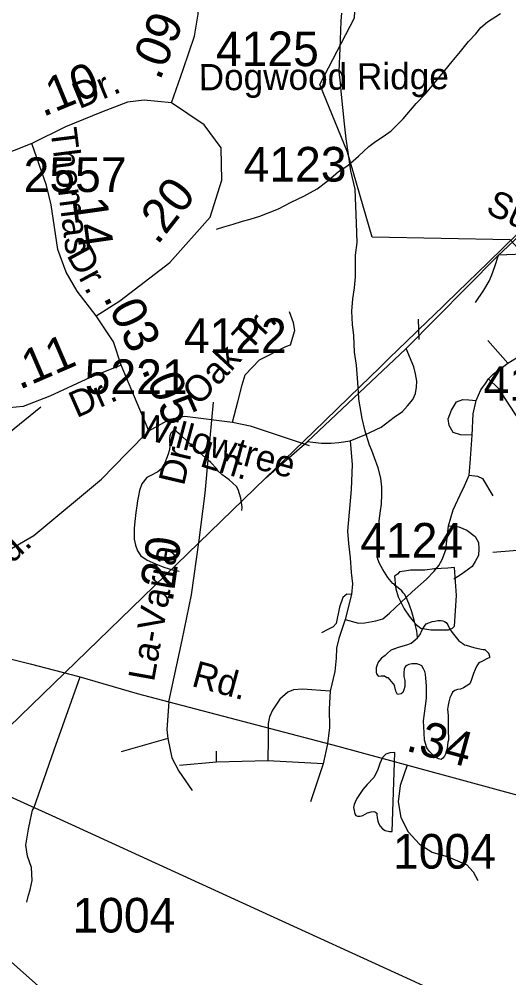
# Model space of a CAD drawing. Extents: x 2169602 to 2449496, y 721995 to 810662.
# Drawn here: x 2387442 to 2389212, y 765731 to 769191 of the extents above; entities that cross this region are included whole.
import ezdxf

# ---------------------------------------------------------------- set-up
doc = ezdxf.new("R2010")
doc.units = 0
doc.layers.add('Default', color=7, linetype='Continuous')

msp = doc.modelspace()

# ---------------------------------------------------------------- linework, layer by layer
at = {"layer": 'Default'}
for p, q in [((2388888.2, 768035.6), (2388885.1, 768108.4)), ((2389208.7, 767949), (2389135.5, 768030.9)), ((2388643, 767114.7), (2388620.1, 767024.6)), ((2387568.8, 766553.9), (2387662.8, 766816.8)), ((2387494.8, 766343.6), (2387568.8, 766553.9)), ((2388156, 766509.2), (2388156, 766548.5)), ((2388156, 766509.2), (2388021.7, 766496.6)), ((2388340.5, 766514.1), (2388156, 766509.2)), ((2388540.4, 766502.6), (2388340.5, 766514.1)), ((2388540.4, 766502.6), (2388494.5, 766366.1))]:
    msp.add_line(p, q, dxfattribs=at)
for points in [[(2386380.1, 765643.4), (2386857.9, 766106.2), (2386916.4, 766162.9), (2386960.4, 766205.5), (2388333.9, 767535.6), (2388482.6, 767665.6), (2388839.5, 768000.9), (2389171, 768336), (2391030.3, 770080.7), (2393764.7, 772758.1), (2394526.4, 773595), (2394852.5, 773868.2), (2394973.7, 773986.6), (2394998.1, 774010.6), (2395018.6, 774030.8), (2395083, 774094), (2395207.8, 774217.2), (2395509.9, 774514.3), (2395511.9, 774516.4), (2395846.4, 774839.9), (2396368, 775322.6), (2396469.9, 775429.5)], [(2391073.6, 764947.2), (2391178.6, 766960.8), (2390837.4, 766875.9), (2390242.1, 766812.3), (2390226.7, 766354.4), (2389410.2, 766177.4), (2389443.8, 768148.7), (2389216.4, 768394.4), (2388718.4, 768404), (2388629, 768711.2), (2388529.1, 768955.2), (2388654.4, 769196.1), (2388670.2, 769505.2), (2388617.3, 769865), (2388811.9, 770134.5), (2389300.7, 770249.9), (2390705.1, 770262.3), (2391005.7, 772988.7), (2392249.8, 773007.3), (2392264.1, 772753.4), (2392724.3, 772714.7), (2392730.4, 771054.6), (2393230.3, 770963)], [(2386380.1, 765643.4), (2386857.9, 766106.2), (2386916.4, 766162.9), (2386960.4, 766205.5), (2388333.9, 767535.6), (2388482.6, 767665.6), (2388839.5, 768000.9), (2389171, 768336), (2391030.3, 770080.7), (2393764.7, 772758.1)], [(2387993.1, 768889.1), (2388034.9, 769009.5), (2388075.7, 769129.9), (2388089.3, 769209.5), (2388084.1, 769344.6)], [(2388155.8, 768433.4), (2388181.9, 768441.2), (2388215.7, 768451.4), (2388249.7, 768461.8), (2388277.4, 768469.7), (2388311.5, 768480), (2388345.7, 768493.9), (2388379.5, 768506.2), (2388425.3, 768530.5), (2388471, 768552.8), (2388519.2, 768578.8), (2388558.9, 768608.8), (2388596.7, 768640.9), (2388630.5, 768663.3), (2388668.7, 768697.4), (2388706.2, 768731.4), (2388730, 768749.7), (2388758.1, 768767.7), (2388786.1, 768787.8), (2388829.6, 768832), (2388877.2, 768886.4), (2388911.2, 768922.2), (2388947.3, 768964.6), (2388980.9, 769006.6), (2389006.8, 769038.8), (2389036.5, 769074.9), (2389066.5, 769110.9), (2389092.3, 769139), (2389110.1, 769161.1), (2389134.3, 769181.4), (2389181.7, 769211.5)], [(2388669.8, 767825), (2388665.7, 767879.5), (2388661.1, 767941.8), (2388653.6, 767989.6), (2388651.1, 768049.6), (2388646.8, 768089.6), (2388644.5, 768137.4), (2388648.4, 768181.4), (2388654.2, 768221.5), (2388657.9, 768261.5), (2388657.9, 768309.4), (2388657.7, 768339.4), (2388663.8, 768385.5), (2388661.3, 768455.3), (2388656.6, 768577.2), (2388640.4, 768643.4), (2388632, 768703), (2388624, 768759.1), (2388617.7, 768813.2), (2388611.5, 768872.9), (2388606.8, 768919), (2388603.1, 768960.9), (2388598.6, 769003), (2388602.5, 769086.8), (2388604.3, 769149), (2388606, 769184.8), (2388607.8, 769213)], [(2387993.1, 768889.1), (2387893.7, 768898.5), (2387833.5, 768891.2), (2387739.3, 768855.6), (2387609.6, 768803.2), (2387487.7, 768742.5)], [(2387721, 768120.5), (2387806.3, 768174.9), (2387986.3, 768313.1), (2388132.8, 768476.5), (2388174.6, 768610.5), (2388172.5, 768726.8), (2388111.3, 768810.5), (2387993.1, 768889.1)], [(2387487.7, 768742.5), (2387231.8, 768641.9), (2386991.7, 768536.2)], [(2387721, 768120.5), (2387651.4, 768209.5), (2387611.7, 768278.6), (2387582.4, 768360.3), (2387557.8, 768521.5), (2387541, 768590.6), (2387487.7, 768742.5)], [(2386380.1, 765643.5), (2386857.9, 766106.2), (2386916.4, 766162.9), (2386960.4, 766205.5), (2388333.9, 767535.6), (2388505.9, 767702.1), (2388676.1, 767867), (2388744, 767932.7), (2388776, 767963.6), (2388815.8, 768002.1), (2388837.1, 768023), (2388922.4, 768105.7), (2388935.7, 768118.4), (2389025.9, 768205.9), (2389135.6, 768312), (2389194.1, 768368.8), (2389200.2, 768374.7), (2389278.4, 768450.3)], [(2389090.8, 768169), (2389121.3, 768212.7), (2389141, 768245.5), (2389150.8, 768268.4), (2389161.5, 768299), (2389174.7, 768339.7)], [(2389208.7, 767949), (2389254.6, 767978.5), (2389299.3, 768014.5), (2389310.3, 768029.8), (2389319, 768049.5), (2389326.6, 768080), (2389338.6, 768149.4), (2389341.9, 768223.7), (2389341.9, 768266.2), (2389339.7, 768290.3), (2389332.1, 768306.6), (2389317.9, 768323), (2389304.8, 768333.9), (2389281.9, 768341.6), (2389264.4, 768342.7), (2389174.7, 768339.7)], [(2387811.5, 767942.5), (2387782.8, 768026.2), (2387721, 768120.5)], [(2388213.5, 767736.9), (2388232.9, 767810.4), (2388248, 767870.9), (2388258.8, 767907.6), (2388310.7, 767961.6), (2388405.7, 768009.2), (2388422.9, 768015.6), (2388438.1, 768067.5), (2388433.7, 768095.6), (2388418.6, 768134.5)], [(2388638.7, 767669.5), (2388691.1, 767690.7), (2388750.1, 767718), (2388797, 767754.1), (2388827.6, 767774.8), (2388846.1, 767795.6), (2388864.7, 767818.5), (2388874.5, 767840.4), (2388877.8, 767863.3), (2388878.9, 767884), (2388874.5, 767911.3), (2388868, 767936.4), (2388840.9, 768002.3)], [(2387811.5, 767942.5), (2387699, 767897.4), (2387553.6, 767830.4), (2387456.8, 767792.7), (2387381.5, 767786.4), (2387288.3, 767802.1)], [(2387911.5, 767704.8), (2387849.2, 767851.4), (2387811.5, 767942.5)], [(2389138.8, 767893.3), (2389156.3, 767910.8), (2389179.2, 767928.3), (2389208.7, 767949)], [(2389094, 767815.2), (2389110.4, 767852.9), (2389127.9, 767875.8), (2389138.8, 767893.3)], [(2389138.8, 767893.3), (2389174.8, 767858.4), (2389205.4, 767809.2), (2389242.6, 767751.9), (2389265.5, 767724.6), (2389278.6, 767707.1)], [(2387983.7, 766727.2), (2388031.1, 766949), (2388065.4, 767112.9), (2388093.2, 767310), (2388114.6, 767480.3), (2388126, 767614), (2388144.9, 767808.8)], [(2388795.9, 767152.8), (2388792.8, 767154.5), (2388774.7, 767176.3), (2388756.3, 767204.2), (2388744.8, 767226.2), (2388738.4, 767242.2), (2388736.4, 767252.3), (2388736.6, 767274.1), (2388736.2, 767292.4), (2388736, 767314.3), (2388738, 767334.3), (2388741.9, 767362.1), (2388743.6, 767380.1), (2388747.5, 767416), (2388751.6, 767440.2), (2388753.2, 767476), (2388753.4, 767502.4), (2388749.3, 767534.2), (2388739.1, 767572.2), (2388726.8, 767608.2), (2388717.1, 767634), (2388708.5, 767653.9), (2388692.5, 767703.8), (2388682.3, 767749.6), (2388674.1, 767791.8), (2388670.2, 767819.6), (2388669.8, 767825)], [(2389078.7, 767690.2), (2389037.3, 767690.7), (2389011, 767699.5), (2388995.8, 767724.6), (2388992.5, 767748.6), (2389004.5, 767780.3), (2389023.1, 767809.8), (2389046, 767818.5), (2389066.7, 767817.4), (2389094, 767815.2)], [(2389078.7, 767690.2), (2389083.1, 767766.1), (2389094, 767815.2)], [(2387520.4, 767790.4), (2387109.2, 767457.9), (2386137.9, 767379.2)], [(2387911.5, 767704.8), (2387986.7, 767747.7), (2388040.7, 767758.5), (2388213.5, 767736.9)], [(2388213.5, 767736.9), (2388277.5, 767723.3), (2388490.5, 767652.2)], [(2386711.3, 766346.6), (2386764.1, 766508.9), (2386866.1, 766897.4), (2386895.4, 766978.1), (2386938.8, 767039.8), (2387000.6, 767112.1), (2387084.3, 767166.5), (2387174.8, 767196.9), (2387283.6, 767212.6), (2387339.1, 767237.7), (2387495, 767327.8), (2387740.4, 767530.9), (2387830.9, 767624.1), (2387911.5, 767704.8)], [(2388155.1, 767569.7), (2388135, 767591.5), (2388115.1, 767607.4), (2388091.1, 767629.3), (2388054.6, 767663.2), (2388024.9, 767690.9), (2388014.6, 767698.9), (2388010.7, 767702.7), (2388006.8, 767704.9), (2387998.6, 767704.9), (2387994.5, 767700.7), (2387991, 767696.8), (2387986.7, 767686.9), (2387985.1, 767676.6), (2387986.9, 767646.7), (2387984.9, 767632.8), (2387980.8, 767620.8), (2387965.2, 767580.6), (2387957.4, 767568.8), (2387943.5, 767556.7), (2387915.6, 767542.7), (2387903.1, 767536.5), (2387885.8, 767514.3), (2387877.6, 767490.4), (2387873.7, 767470.3), (2387869.8, 767452.2), (2387867.8, 767434.3), (2387864.3, 767410.5), (2387860.2, 767378.3), (2387858.4, 767352.2), (2387858.4, 767314.4), (2387862.9, 767292.3), (2387870.5, 767272.4), (2387882.4, 767254.5), (2387904.9, 767238.5), (2387934.8, 767224.6), (2387964.8, 767212.8), (2387996.8, 767203.1), (2388020.4, 767199.1)], [(2389357.3, 765493.2), (2389238.5, 765547.6), (2388843.6, 765729.8), (2388322.2, 765968.2), (2387561.5, 766315.9), (2387500.6, 766343.5), (2387061.4, 766542.1), (2386786.2, 766666.5), (2385752.3, 767165.8), (2385572, 767251), (2385399.7, 767340.2), (2385209.4, 767441.4), (2385079, 767522.7), (2384962.7, 767604.2), (2384887.9, 767663.1)], [(2388483.3, 767666.2), (2388534.9, 767660.7), (2388569.9, 767660.7), (2388597.2, 767662.9), (2388638.7, 767669.5)], [(2388638.7, 767669.5), (2388645.2, 767583.2), (2388641.9, 767493.6), (2388628.8, 767343.5), (2388632.1, 767298.7), (2388638.7, 767246.3), (2388641.9, 767193.3), (2388647.4, 767152.9), (2388643, 767114.7)], [(2389067.8, 767545.5), (2389072.2, 767588.6), (2389078.7, 767690.2)], [(2390536.3, 767677.6), (2390125, 767345.1), (2389153.7, 767266.3)], [(2388246.8, 767417.4), (2388247.8, 767430), (2388243.9, 767461.8), (2388233.4, 767493.8), (2388227.9, 767504), (2388201.2, 767527.8), (2388175.2, 767547.6), (2388161, 767559.5), (2388155.1, 767569.7)], [(2388993.6, 767362.6), (2389010, 767419.9), (2389036.2, 767474.5), (2389051.4, 767507.3), (2389067.8, 767545.5)], [(2389067.8, 767545.5), (2389098.4, 767542.2), (2389117, 767533.5), (2389154.1, 767471.2)], [(2388620.1, 767024.6), (2388668.1, 767011.5), (2388691.1, 767012.6), (2388731.5, 767019.2), (2388756.6, 767026.8), (2388780.6, 767046.5), (2388862.5, 767124), (2388913.9, 767169.3), (2388942.2, 767198.8), (2388958.6, 767219.5), (2388970.6, 767240.3), (2388983.7, 767275.2), (2388993.6, 767362.6)], [(2388993.6, 767362.6), (2389030.7, 767358.2), (2389060.2, 767346.2), (2389089.7, 767324.4), (2389101.7, 767302.5), (2389102.8, 767280.7), (2389101.7, 767255.6), (2389089.7, 767233.7), (2389078.7, 767215.2), (2389039.4, 767186.8), (2389013.2, 767169.3)], [(2389023.2, 767111.3), (2389014.8, 767211.5), (2388991, 767209.4), (2388942.6, 767207), (2388908.8, 767202.8), (2388885, 767202.8), (2388856.9, 767202.5), (2388834.9, 767198.6), (2388816.7, 767196.4), (2388809.1, 767188.3), (2388798.9, 767180.5), (2388799.3, 767170.3), (2388800.9, 767152.6), (2388803, 767134.4), (2388811.6, 767106.4), (2388821.4, 767086.6), (2388833.1, 767062.6), (2388851.4, 767036.7), (2388865.7, 767018.7), (2388877.6, 767004.8), (2388893.8, 766993), (2388929.9, 766987.1), (2388960, 766987.4), (2388994.1, 766987.1), (2389007.8, 766993.2), (2389015.6, 766999.7), (2389023.2, 767111.3)], [(2388881.2, 766958.6), (2388881, 766972.4), (2388879.3, 766982.4), (2388877.1, 766992.4), (2388870.9, 767016.5), (2388864.8, 767038.5), (2388860.7, 767052.1), (2388852.9, 767076.4), (2388844.7, 767096.3), (2388836.3, 767114.3), (2388830.3, 767120), (2388824.6, 767128.2), (2388812.1, 767138.1), (2388802, 767146.2), (2388795.9, 767152.8)], [(2388643, 767114.7), (2388626.7, 767115.8), (2388612.5, 767103.8), (2388599.4, 767068.8), (2388587.3, 767009.3), (2388576.4, 766997.3), (2388557.9, 766987.5), (2388534.9, 766975.5)], [(2386978.7, 767010.8), (2387153.5, 766945.9), (2387482.1, 766864.2), (2387657.9, 766818.1), (2387869.2, 766757.4), (2387983.7, 766727.2)], [(2388620.1, 767024.6), (2388597.2, 766955.8), (2388589.5, 766920.9), (2388588.4, 766884.8), (2388583, 766836.8), (2388566.6, 766765.8)], [(2388881.2, 766958.6), (2388885.3, 766962.4), (2388890.8, 766970.5), (2388897, 766984.6), (2388901.1, 766990.5), (2388907, 767000.5), (2388912.9, 767008.5), (2388923, 767012.7), (2388934.7, 767016.6), (2388944.7, 767018.7), (2388955, 767020.8), (2388964.6, 767021), (2388972.8, 767018.9), (2388979, 767016.8), (2388984.7, 767013.1), (2388991.1, 767005.2), (2388998.9, 766989), (2389007.1, 766977.2), (2389021.2, 766959.3), (2389031.1, 766947.2), (2389045.6, 766937.3), (2389051.4, 766933.2), (2389057.3, 766931.5), (2389085.4, 766923.7), (2389111.2, 766917.7), (2389119.2, 766915.7), (2389125.4, 766916), (2389137.3, 766904), (2389139.7, 766900), (2389141.8, 766892), (2389141.6, 766885.9), (2389137.5, 766884.1), (2389111.6, 766871.8), (2389103.6, 766867.7), (2389096.1, 766857.5), (2389089.9, 766843.8), (2389083.8, 766829.8), (2389076, 766803.8), (2389070.2, 766791.7), (2389058.1, 766783.3), (2389048.3, 766777.6), (2389036.6, 766773.2), (2389026.5, 766771.5), (2389016.5, 766767.4), (2389008.1, 766761.3), (2389002.4, 766749.2), (2388998.5, 766741.3), (2388994.4, 766727.3), (2388992.3, 766715), (2388990.5, 766701.1), (2388992.9, 766677.2), (2388992.5, 766647.2), (2388992.9, 766637), (2388993.1, 766617.2), (2388993.5, 766599.3), (2388993.5, 766589.1), (2388991.3, 766581.3), (2388989.4, 766559.3), (2388985.5, 766543.3), (2388979.6, 766531.2), (2388973.6, 766523.1), (2388967.5, 766519.2), (2388957.4, 766521.1), (2388945.3, 766527), (2388933.2, 766539), (2388923.4, 766549), (2388915.6, 766560.7), (2388911.3, 766572.8), (2388907.2, 766588.8), (2388905.2, 766614.6), (2388905, 766636.6), (2388903.1, 766658.7), (2388907, 766684.5), (2388914.2, 766740.6), (2388914.4, 766756.8), (2388914, 766784.9), (2388912.1, 766812.7), (2388910.3, 766826.8), (2388907.6, 766836.5), (2388903.7, 766846.5), (2388897.8, 766856.7), (2388890, 766860.7), (2388879.5, 766864.7), (2388869.9, 766864.5), (2388861.7, 766864.5), (2388849.8, 766862.3), (2388843.6, 766858.3), (2388837.9, 766854.4), (2388833.6, 766846.1), (2388832.2, 766832.2), (2388832.4, 766818.3), (2388836.1, 766804.4), (2388835.8, 766796.3), (2388836.3, 766782.4), (2388832.4, 766770), (2388828.3, 766760.1), (2388822.5, 766756.1), (2388809.6, 766753.2), (2388803.7, 766765.5), (2388798.5, 766786.1)], [(2388797.7, 766918.5), (2388813.5, 766924.2), (2388835.2, 766930.2), (2388847.3, 766934.1), (2388859.2, 766938.4), (2388873.6, 766950.4), (2388881.2, 766958.6)], [(2388797.7, 766918.5), (2388783.8, 766912.4), (2388773.7, 766902.6), (2388764.3, 766894.3), (2388752, 766884.4), (2388743.8, 766876.3), (2388739.9, 766870.4), (2388736.2, 766860.4), (2388732.3, 766850.1), (2388732.3, 766842.4), (2388732.1, 766834.3), (2388734.1, 766828.3), (2388738.2, 766822.4), (2388742.1, 766820.2), (2388750.3, 766820.6), (2388762.2, 766820.4), (2388770.4, 766814.3), (2388774.7, 766814.8), (2388798.5, 766786.1)], [(2388566.6, 766765.8), (2388466.1, 766772.9), (2388433.4, 766770.7), (2388413.7, 766762), (2388384.2, 766736.9), (2388358, 766696.5), (2388347.1, 766672.4), (2388342.7, 766648.4), (2388342.7, 766594.9), (2388340.5, 766514.1)], [(2388566.6, 766765.8), (2388562.2, 766701.9), (2388563.3, 766634.2), (2388556.8, 766575.2), (2388540.4, 766502.6)], [(2387983.7, 766727.2), (2387975.7, 766627.3), (2387979.3, 766594.3)], [(2387983.7, 766727.2), (2388593.3, 766566.8), (2389323.7, 766367.8), (2389626.6, 766283), (2389727.1, 766233.8)], [(2387979.3, 766594.3), (2387810.7, 766546.6)], [(2387979.3, 766594.3), (2387994, 766524.6), (2388019.7, 766476.9), (2388067.3, 766407.2)], [(2388800, 766544.6), (2388781.3, 766542.5), (2388767.6, 766538.5), (2388755.3, 766526.6), (2388745.6, 766504.5), (2388737.8, 766482.6), (2388729.6, 766464.3), (2388723.7, 766454.3), (2388700.3, 766428.2), (2388684.1, 766410.4), (2388672.2, 766392.3), (2388662.6, 766378), (2388656.4, 766364.3), (2388652.5, 766355.9), (2388650.5, 766346.1), (2388652.3, 766334.1), (2388654.6, 766328), (2388656.6, 766320), (2388658.7, 766316.1), (2388664.6, 766314.3), (2388674.5, 766314.1), (2388684.5, 766316.2), (2388700.7, 766326.3), (2388714, 766330.4), (2388724.3, 766330.5), (2388730.2, 766328.3), (2388734.3, 766324.5), (2388734.6, 766320.4), (2388736.4, 766308.4), (2388738.7, 766296.7), (2388740.3, 766288.7), (2388746.7, 766278.4), (2388754.9, 766268.7), (2388764.9, 766262.7), (2388780.9, 766258.7), (2388790.5, 766258.8), (2388800, 766544.6)], [(2388844.6, 766498.3), (2388819.2, 766425.4), (2388811.5, 766365.7), (2388821.1, 766309.8), (2388848.1, 766257.8), (2388888.5, 766213.4), (2388934.7, 766184.5), (2388992.5, 766167.2), (2389059.9, 766138.3), (2389083, 766113.2), (2389100.3, 766082.4)], [(2387470.2, 766003.6), (2387475.8, 766028.6), (2387482.7, 766048), (2387489.7, 766081.4), (2387486.9, 766128.6), (2387472.1, 766169.6), (2387466, 766209.7), (2387475.7, 766267.7), (2387483, 766301.8), (2387490.5, 766336.1), (2387494.8, 766343.6)], [(2386952.2, 766197.6), (2387279.1, 765900.4), (2387414.5, 765786.8), (2387510.6, 765701.6)]]:
    msp.add_lwpolyline(points, dxfattribs=at)

# ---------------------------------------------------------------- texts
for s, height, rotation, p in [('.09', 125, 67.8664, (2387951, 768967.1)), ('.10', 125, 22.3145, (2387528.1, 768837.5)), ('Dogwood Ridge', 95, 0.2713, (2388091.2, 768934.4)), ('Dr.', 95, 22.3145, (2387659.2, 768865.9)), ('Thomas', 95, 277.1412, (2387555.2, 768793.6)), ('.20', 125, 51.8538, (2387941.8, 768373.1)), ('.14', 125, 278.0835, (2387627.8, 768586.4)), ('Sunset Ct.', 95, 334.9746, (2389124.1, 768493.5)), ('Dr.', 95, 298.3834, (2387612.2, 768339.8)), ('.03', 125, 296.0285, (2387745, 768187.5)), ('Oak Tr.', 95, 47.3023, (2388092.4, 767791.9)), ('.11', 125, 23.3424, (2387443.2, 767852.5)), ('.05', 125, 293.9038, (2387882.9, 767927.2)), ('Dr.', 95, 23.7566, (2387649.5, 767750.6)), ('Willowtree', 95, 344.9257, (2387859.3, 767685.6)), ('Ln.', 95, 343.0664, (2388091.4, 767578.6)), ('Dr.', 95, 76.6801, (2388037.5, 767504)), ('Rd.', 95, 42.4558, (2387348.3, 767161.4)), ('.20', 125, 81.9616, (2387996.8, 767083.9)), ('La-Varra', 95, 79.7814, (2387929.3, 766796.9)), ('Rd.', 95, 344.6937, (2388061.5, 766785)), ('.34', 125, 344.7624, (2388835.8, 766551.7))]:
    msp.add_text(s, height=height, rotation=rotation, dxfattribs=at).set_placement(p)
for s, p in [('4125', (2388153.4, 769021.8)), ('4123', (2388253.3, 768605.2)), ('2557', (2387458.5, 768567.4)), ('4122', (2388037.3, 767986.5)), ('5221', (2387679.2, 767838.2)), ('4123', (2389120.3, 767813.7)), ('4124', (2388674.8, 767247.6)), ('1004', (2388793.1, 766124.9)), ('1004', (2387634.9, 765894.2))]:
    msp.add_text(s, height=125, dxfattribs=at).set_placement(p)

doc.saveas('drawing.dxf')
